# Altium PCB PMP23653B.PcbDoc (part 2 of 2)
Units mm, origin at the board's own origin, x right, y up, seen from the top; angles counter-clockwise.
Board outline 60 x 20 mm, 4 copper layers (Top Layer, Layer 2, Layer 3, Bottom Layer), stack 1.509 mm thick; 89 components, 44 nets, 290 pads, 82 vias.
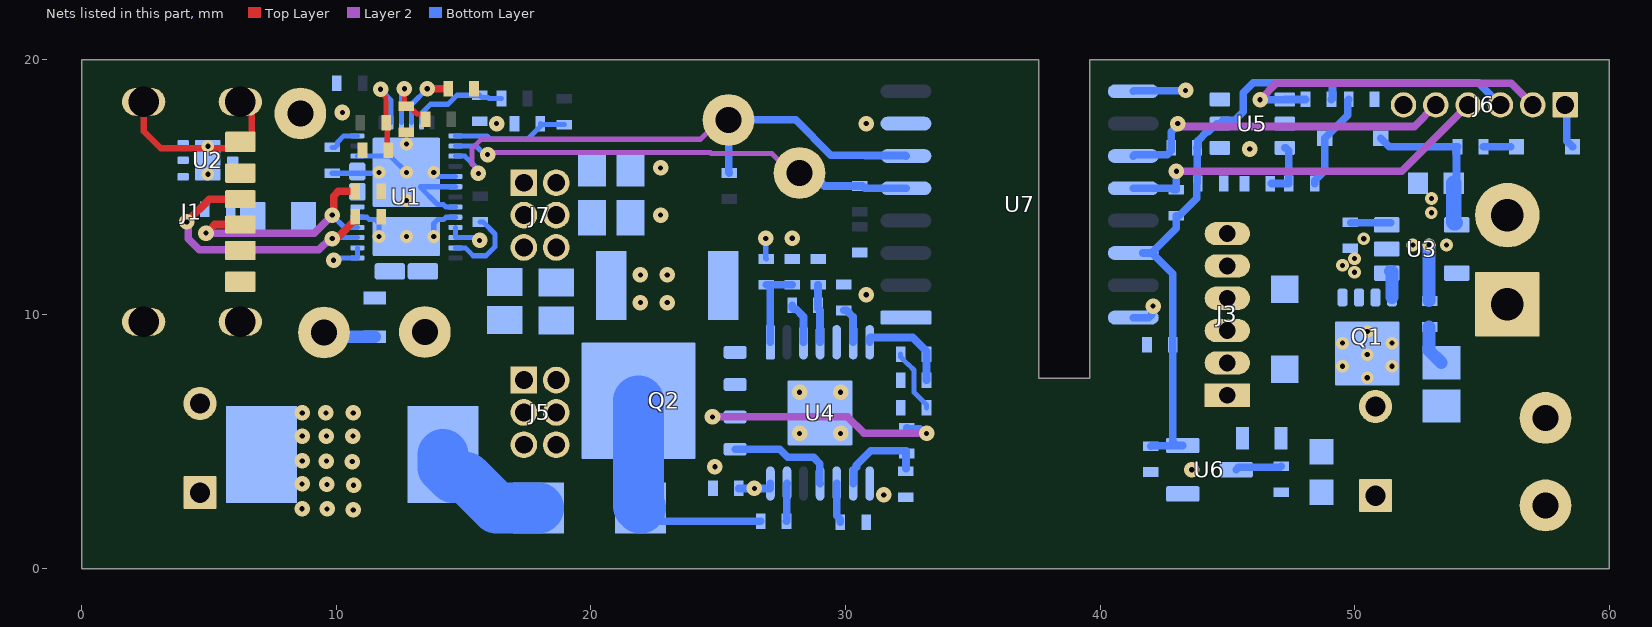
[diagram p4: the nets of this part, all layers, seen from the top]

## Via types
v1: diameter 0.61, hole 0.203, Top Layer to Bottom Layer, tented both sides, 56 vias
v2: diameter 0.5, hole 0.203, Top Layer to Bottom Layer, tented both sides, 9 vias
v3: diameter 0.5, hole 0.2, Top Layer to Bottom Layer, tented both sides, 9 vias
v4: diameter 0.5, hole 0.2, Top Layer to Bottom Layer, 8 vias

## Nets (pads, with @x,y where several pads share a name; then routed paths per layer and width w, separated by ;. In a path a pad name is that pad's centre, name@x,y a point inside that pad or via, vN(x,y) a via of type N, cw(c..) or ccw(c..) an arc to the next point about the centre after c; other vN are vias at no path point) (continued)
3V3S: C21.2 C27.2 C28.2 J6.3 R12.2 R13.2 R26.2 U5.5 U6.2 U7.14 | length 29.4
  Bottom Layer w0.3: U7.14@41.671,12.415 U7.14@42.036,12.415 ; C28.2@42,4.823 42.013,4.836 43.236,4.836 U6.2@43.249,4.85 43.008,4.85 42.858,5 C27.2@42.858,8.8 42.858,11.593 U7.14@42.036,12.415 ; R26.2@49.089,18.445 49.13,18.486 49.13,18.995 49.235,19.1 ; J6.3@55.73,18.23 54.86,19.1 49.235,19.1 ; U7.14@42.036,12.415 43,13.379 R12.2@43,13.877 43.114,13.877 43.801,14.564 43.801,15.136 43.825,15.159 43.825,16.528 R13.2@43.808,16.545 43.849,16.586 43.849,16.828 44.19,17.17 44.256,17.17 44.581,17.495 U5.5@44.706,17.495 44.831,17.62 45.29,17.62 45.63,17.959 45.63,18.706 46.023,19.1 49.235,19.1
ADCIN1: R1.2 R5.2 U1.2 | length 4
  Top Layer w0.2: v1(11.735,18.848) 11.735,18.737 11.953,18.52 R1.2@11.953,17.536 11.997,17.493 11.997,16.496 R5.2@12.04,16.452
  Bottom Layer w0.2: v1(11.735,18.848) 11.735,18.822 12.15,18.408 U1.2@12.15,17.541
ADCIN2: R2.1 R6.1 U1.3 | length 3.1
  Top Layer w0.2: v1(12.673,18.862) 12.673,18.251 R6.1@12.75,18.174 12.864,18.174 13.168,17.871 13.406,17.871 13.497,17.78 R2.1@13.497,17.666
  Bottom Layer w0.2: U1.3@12.55,17.541 12.55,18.628 12.673,18.751 v1(12.673,18.862)
ADCIN3: R3.1 R7.1 U1.5 | length 3.8
  Bottom Layer w0.2: U1.5@13.35,17.541 13.35,17.911 13.696,18.257 14.383,18.257 14.735,18.609 R7.1@15.627,18.609 15.718,18.518 15.96,18.518 15.997,18.482 R3.1@16.487,18.482
ADCIN4: R4.1 R8.1 U1.7 | length 4.7
  Bottom Layer w0.2: U1.7@14.675,17.016 15.919,17.016 16.045,16.89 17.521,16.89 18.011,17.381 R8.1@18.011,17.495 18.05,17.456 R4.1@18.96,17.456
CC1: C5.2 J1.A5 U1.28 | length 11.5
  Top Layer w0.3: v1(4.117,13.632) 5.015,14.53 J1.A5@6.226,14.53 ; v1(9.836,12.979) 9.896,13.038 10.063,13.038 10.742,13.717 C5.2@10.742,13.831
  Layer 2 w0.3: v1(4.117,13.632) 4.177,13.573 4.177,12.968 4.606,12.539 9.312,12.539 9.753,12.979 v1(9.836,12.979)
  Bottom Layer w0.2: v1(9.836,12.979) 9.873,13.016 U1.28@10.825,13.016
CC2: C4.2 J1.B5 U1.29 | length 9.6
  Top Layer w0.3: v1(4.877,13.194) 5.213,13.53 J1.B5@6.226,13.53 ; v1(9.836,13.9) 9.896,13.959 9.896,14.647 10.08,14.831 C4.2@10.742,14.831
  Layer 2 w0.3: v1(4.877,13.194) 9.125,13.194 9.831,13.9 v1(9.836,13.9)
  Bottom Layer w0.2: v1(9.836,13.9) 10.32,13.416 U1.29@10.825,13.416
GND: C1.1 C2.2 C3.2 C4.1 C5.1 C6.1 C7.1 C10.1 C11.2 C12.2 C13.2 C14.2 C19.1 C20.1 C22.1 C23.2 C24.2 C25.1 C30.1 J1.1 J1.2 J1.3 J1.4 J1.A12 J1.B12 R5.1 R6.2 R7.2 R8.2 R23.1 R24.2 R25.2 TP3.1 U1.11 U1.12 U1.14 U1.16 U1.17 U1.26 U1.27 U1.31 U1.34 U1.35 U1.36 U1.39 U2.1 U2.2 U2.3 U2.7@4.95,16.055 U4.5 U4.8 U4.15 U7.1 U7.7 | length 20.4
  Top Layer w0.254: J1.3@2.426,18.35 2.426,17.196 3.096,16.526 6.226,16.526 J1.B12@6.226,16.78 6.277,16.831 6.345,16.763 6.379,16.763 6.67,17.053 6.67,17.959 6.279,18.35 J1.1@6.226,18.35
  Bottom Layer w0.2: C1.1@9.836,15.547 11.641,15.547 v3(11.675,15.581) ; v1(9.89,12.129) 10.001,12.129 10.088,12.216 U1.26@10.825,12.216 U1.27@10.825,12.616 ; U1.36@10.825,16.216 12.115,16.216 v3(12.75,15.581) ; U1.39@13.298,14.999 13.975,14.321 14.2,14.321 14.305,14.216 U1.14@14.675,14.216 ; U1.39@13.315,15.016 U1.12@14.675,15.016 ; U1.39@13.825,15.566 13.975,15.416 U1.11@14.675,15.416 ; U1.16@14.675,13.416 U1.17@14.675,13.016 15.41,13.016 15.516,12.91 v1(15.627,12.91)
  Bottom Layer w0.5: TP3.1@9.516,9.289 9.68,9.125 11.496,9.125 C2.2@11.5,9.121
  other v1: 31.5,2.912 24.87,4.013 28.195,5.323 29.805,5.323 28.195,6.942 29.805,6.942 21.942,10.467 23,10.467 30.813,10.772 21.942,11.553 23,11.553 27.906,12.989 22.736,13.9 22.736,15.756 16.295,17.495 30.813,17.495 10.235,17.932
  other v3: 12.75,14.471 13.825,15.581 12.75,16.691
  other v4: 4.95,15.505 4.95,16.605
NetC1_2: C1.2 U1.38 | length 1.2
  Bottom Layer w0.2: C1.2@9.836,16.563 9.951,16.563 10.041,16.654 10.041,16.768 10.29,17.016 U1.38@10.825,17.016
NetC2_1: C2.1 L1.2 U1.23 U1.24 U1.25 U1.32 U1.33
NetC3_1: C3.1 J1.A9 J1.B9 L1.1 TP1.1 U2.4 U2.5 U2.6
NetC7_2: C7.2 U1.4 | length 2.4
  Top Layer w0.3: v1(13.569,18.862) C7.2@14.392,18.862
  Bottom Layer w0.2: U1.4@12.95,17.541 12.95,18.242 v1(13.569,18.862)
NetC9_1: C9.1 U3.3 | length 1.6
  Bottom Layer w0.3: C9.1@49.853,13.596 U3.3@51.411,13.596
NetC18_1: C18.1 R17.1 | length 1.6
  Bottom Layer w0.5: C18.1@52.92,9.508 52.92,8.588 R17.1@53.408,8.1
NetC20_2: C20.2 U4.10 | length 1.6
  Bottom Layer w0.3: U4.10@29.65,3.357 29.65,2.095 29.797,1.948 C20.2@29.797,1.834
NetC22_2: C22.2 R20.1 U4.9 | length 3.7
  Bottom Layer w0.3: U4.9@30.3,3.357 30.3,3.875 30.43,4.005 30.43,4.08 30.999,4.649 32.374,4.649 C22.2@32.374,3.948
NetC23_1: C23.1 R21.1 U4.7 | length 3.8
  Bottom Layer w0.3: U4.7@30.95,8.908 30.95,9.074 30.969,9.092 32.642,9.092 33.182,8.552 R21.1@33.182,8.438 C23.1@33.182,7.42
NetC24_1: C24.1 R21.2 | length 2.5
  Bottom Layer w0.2: R21.2@32.166,8.438 32.166,8.323 32.465,8.025 32.481,8.025 32.692,7.814 32.692,6.939 33.182,6.449 C24.1@33.182,6.334
NetC25_2: C25.2 U4.6 | length 1.5
  Bottom Layer w0.3: C25.2@29.924,10.156 30.039,10.156 30.292,9.903 30.292,8.916 U4.6@30.3,8.908
NetC26_1: C26.1 D3.1 R27.2 | length 3.9
  Bottom Layer w0.3: R27.2@48.431,15.143 48.431,15.257 48.823,15.649 D3.1@48.823,16.925 49.727,17.828 49.727,18.405 C26.1@49.767,18.445
NetD1_1: D1.1 R15.2 | length 1.1
  Bottom Layer w0.3: R15.2@55.06,16.586 D1.1@56.135,16.586
NetD2_1: D2.1 D4.1 | length 4.9
  Bottom Layer w2: D2.1@14.194,4.5 14.194,3.992 14.591,3.595 15.099,3.595 16.297,2.397 D4.1@17.942,2.397
NetD4_2: D4.2 J5.1 J5.2 J5.3 J5.4 J5.5 J5.6 Q2.5 Q2.6 Q2.7 Q2.8 Q2.9@21.865,6.607 R19.2 | length 9.2
  Bottom Layer w0.3: D4.2@21.942,2.397 22.459,1.88 R19.2@26.667,1.88
  Bottom Layer w2: Q2.9@21.865,6.607 21.865,2.474 D4.2@21.942,2.397
NetQ1_4: Q1.4 U3.1 | length 1.1
  Bottom Layer w0.5: U3.1@51.411,11.696 51.446,11.696 51.471,11.671 Q1.4@51.471,10.665
NetQ2_1: Q2.1 Q2.2 Q2.3 R20.2 R23.2 | length 9.5
  Layer 2 w0.3: v1(24.775,5.972) 24.78,5.977 30.076,5.977 30.728,5.325 v1(33.182,5.325)
  Bottom Layer w0.3: R20.2@32.415,5.548 32.455,5.507 32.916,5.507 33.099,5.325 v1(33.182,5.325)
NetQ2_4: Q2.4 U4.11 | length 4.3
  Bottom Layer w0.3: Q2.4@25.665,4.702 27.412,4.702 27.73,4.385 28.743,4.385 28.992,4.136 28.992,3.365 U4.11@29,3.357
NetR9_1: R9.1 U1.18 | length 3.1
  Bottom Layer w0.2: U1.18@14.675,12.616 15.065,12.616 15.377,12.305 15.878,12.305 16.232,12.659 16.232,13.162 15.765,13.629 R9.1@15.651,13.629
NetR14_2: R14.2 R27.1 U5.3 | length 2.2
  Bottom Layer w0.3: R14.2@46.735,15.143 R27.1@47.415,15.143 47.415,16.42 47.29,16.545 U5.3@47.256,16.545
NetR18_2: R18.2 R24.1 U4.1 | length 3.4
  Bottom Layer w0.3: U4.1@27.05,8.908 27.05,11.116 27.004,11.162 R18.2@26.89,11.162 R24.1@27.906,11.162
NetR19_1: R19.1 U4.13 | length 1.5
  Bottom Layer w0.3: R19.1@27.683,1.88 27.692,1.889 27.692,3.349 U4.13@27.7,3.357
NetR22_1: R22.1 R25.1 U4.4 | length 2.2
  Bottom Layer w0.3: R22.1@28.922,10.239 29,10.161 U4.4@29,8.908 ; R22.1@28.922,10.354 R25.1@28.922,11.162
NetR22_2: R22.2 U4.3 | length 1.7
  Bottom Layer w0.3: R22.2@27.906,10.354 27.906,10.239 27.946,10.199 28.06,10.199 28.35,9.909 U4.3@28.35,8.908
NetU1_15: U1.15 U1.30 U1.40 | length 2.9
  Bottom Layer w0.2: U1.30@10.825,13.816 11.195,13.816 11.29,13.721 11.525,13.721 11.675,13.571 v3(11.675,13.056) ; v3(13.825,13.056) 13.825,13.571 13.975,13.721 14.21,13.721 14.305,13.816 U1.15@14.675,13.816
  other v3: 12.75,13.056
PPHV: C10.2 C11.1 C12.1 C13.1 C14.1 C19.2 D2.2 J7.1 J7.2 J7.3 J7.4 J7.5 J7.6 R18.1 TP2.1 U1.20 U1.21 U1.22 U4.14 | length 2.2
  Bottom Layer w0.2: v1(26.868,12.985) 26.868,12.2 R18.1@26.89,12.178
  Bottom Layer w0.3: C19.2@25.808,3.163 27.031,3.163 27.05,3.182 U4.14@27.05,3.357
  other v1: 10.665,2.318 8.651,2.367 9.635,2.357 26.42,3.163 10.676,3.29 8.651,3.34 9.626,3.319 10.625,4.216 8.66,4.242 9.604,4.236 8.66,5.222 9.604,5.222 10.651,5.222 8.66,6.132 9.589,6.132 10.665,6.132
SCL1: R11.1 TP5.1 U1.9 U7.6 | length 22.6
  Layer 2 w0.2: v1(15.577,15.538) 15.577,15.649 15.332,15.895 15.332,16.527 15.686,16.881 24.299,16.881 25.059,17.641 TP5.1@25.4,17.641
  Bottom Layer w0.2: U1.9@14.675,16.216 15.045,16.216 15.499,15.762 15.499,15.617 v1(15.577,15.538)
  Bottom Layer w0.3: R11.1@25.433,15.553 25.416,15.569 25.416,17.625 TP5.1@25.4,17.641 28.041,17.641 29.427,16.255 30.769,16.255 30.784,16.24 32.359,16.24 U7.6@32.374,16.225
SCL2: J6.5 R13.1 U7.11 | length 13.3
  Layer 2 w0.3: v1(43.054,17.495) 43.138,17.495 43.253,17.38 52.34,17.38 J6.5@53.19,18.23
  Bottom Layer w0.3: U7.11@41.305,16.225 41.352,16.271 42.633,16.271 42.792,16.431 R13.1@42.792,16.545 42.792,17.176 43.054,17.438 v1(43.054,17.495)
SDA1: R10.1 TP4.1 U1.8 U7.5 | length 18.3
  Layer 2 w0.2: v1(15.937,16.276) 16.047,16.276 16.132,16.361 24.689,16.361 24.725,16.325 27.104,16.325 27.874,15.555 TP4.1@28.195,15.555
  Bottom Layer w0.2: U1.8@14.675,16.616 15.486,16.616 15.826,16.276 v1(15.937,16.276)
  Bottom Layer w0.3: TP4.1@28.195,15.555 28.664,15.555 29.174,15.045 R10.1@30.553,15.045 ; R10.1@30.668,15.045 30.757,14.955 U7.5@32.374,14.955
SDA2: J6.4 R12.1 U7.12 | length 15
  Layer 2 w0.3: v1(43,15.625) 51.855,15.625 J6.4@54.46,18.23
  Bottom Layer w0.3: U7.12@41.305,14.955 42.824,14.955 42.886,14.893 R12.1@43,14.893 v1(43,15.625)
SGND: C15.1 C16.1 C17.1 C21.1 C26.2 C27.1 C28.1 J2.2 J3.1 J3.2 J3.3 J6.6 R14.1 R16.1 TP7.1 U5.2 U5.4 U5.6 U6.1 U7.9 U7.16 | length 3.2
  Bottom Layer w0.3: U7.16@41.305,9.875 41.915,9.875 42.027,9.987 42.027,10.267 v1(42.086,10.326) ; U7.9@41.305,18.765 41.323,18.783 43.339,18.783 v1(43.357,18.801)
  other v1: 43.599,3.9 45.878,16.498
VIN_MAG: J6.2 R26.1 U5.1 | length 13.1
  Layer 2 w0.3: v1(46.284,18.435) 46.93,19.08 56.15,19.08 J6.2@57,18.23
  Bottom Layer w0.3: v1(46.284,18.435) 46.289,18.44 47.251,18.44 U5.1@47.256,18.445 R26.1@48.073,18.445
VMON: C8.1 D3.2 R15.1 U3.4 | length 6.3
  Bottom Layer w0.3: D3.2@51.023,16.925 51.362,16.586 R15.1@54.044,16.586 54.004,16.545 54.004,15.273 C8.1@53.89,15.159
  Bottom Layer w0.6: C8.1@53.89,15.159 53.89,13.621 53.915,13.596 U3.4@53.961,13.596
VOUT: C15.2 C16.2 C17.2 D1.2 D5.C J2.1 J6.1 Q1.5 Q1.6 Q1.7 Q1.8 Q1.9 R16.2 R17.2 TP6.1 U3.5 U6.3 | length 3.6
  Bottom Layer w0.3: U6.3@45.349,3.9 45.438,3.988 47.076,3.988 C17.2@47.116,4.029 ; J6.1@58.27,18.23 58.335,18.165 58.335,16.812 D1.2@58.561,16.586
  other v3: 50.496,7.512
  other v4: 49.521,7.965 51.471,7.965 50.496,8.417 49.521,8.87 51.471,8.87 50.496,9.322
VSEC: C8.2 C9.2 C18.2 D5.A J3.4 J3.5 J3.6 Q1.1 Q1.2 Q1.3 U3.2 | length 2.2
  Bottom Layer w0.5: C18.2@52.92,10.543 v2(52.92,12.729)
  other v2: 49.999,11.657 49.521,11.927 49.999,12.191 52.288,12.729 53.611,12.729 50.357,12.975 53.016,13.991 53.02,14.556
pads on no net: Q1.9A Q1.9B Q1.9C Q1.9D Q2.9@21.47,5.157 Q2.9@21.47,6.607 Q2.9@21.47,8.057 Q2.9@22.32,6.607 Q2.9@23.25,5.157 Q2.9@23.25,6.607 Q2.9@23.25,8.057 U1.6 U1.10 U1.13 U1.19 U1.37 U2.7@4.95,15.605 U2.7@4.95,16.505 U4.2 U4.12 U7.2 U7.4 U7.8 U7.10 U7.13 U7.15

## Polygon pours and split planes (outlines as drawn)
SGND on Top Layer "TOP_LAYER_SGND_P014" (solid, remove dead copper, pour order 14): 41.581,20.019 41.581,0 60.018,0 60.018,20.019
GND on Top Layer "TOP_LAYER_GND_P008" (solid, remove dead copper, pour order 8): 0,20.019 0,0 32.415,0 32.415,20.019
NetC3_1 on Top Layer "TOP_LAYER_NETC3_1_P000" (solid, remove dead copper, pour order 0): 5.5,18.949 5.5,12.129 9.686,12.129 9.686,18.949
SGND on Bottom Layer "BOTTOM_LAYER_SGND_P011" (solid, remove dead copper, pour order 11): 41.581,20 41.581,0 60,0 60,20
VOUT on Bottom Layer "BOTTOM_LAYER_VOUT_P010" (solid, remove dead copper, pour order 10): 46.362,11.935 46.362,3.78 60,3.78 60,11.935
VSEC on Bottom Layer "BOTTOM_LAYER_VSEC_P001" (solid, remove dead copper, pour order 1): 52.016,13.776 52.012,13.781 52.012,15.715 53.263,15.715 53.357,15.622 53.357,13.98 54.326,13.98 54.53,13.776 54.53,11.966 53.535,11.966 51.725,10.156 44.048,10.156 44.048,13.776
GND on Bottom Layer "BOTTOM_LAYER_GND_P009" (solid, remove dead copper, pour order 9): 0,20.008 0,0 32.415,0 32.415,20.008
PPHV on Bottom Layer "BOTTOM_LAYER_PPHV_P004" (solid, remove dead copper, pour order 4): 3.75,16.605 3.75,10.505 20.62,10.505 20.62,16.605
NetQ2_1 on Bottom Layer "BOTTOM_LAYER_NETQ2_1_P007" (solid, remove dead copper, pour order 7): 24.365,12.598 24.365,5.547 26.5,5.547 26.5,12.598
NetD4_2 on Bottom Layer "BOTTOM_LAYER_NETD4_2_P006" (solid, remove dead copper, pour order 6): 15.959,8.908 15.959,3.883 24.2,3.883 24.2,8.908
PPHV on Bottom Layer "BOTTOM_LAYER_PPHV_P005" (solid, remove dead copper, pour order 5): 0,12.008 0,0 15.627,0 15.627,12.008
NetC2_1 on Bottom Layer "BOTTOM_LAYER_NETC2_1_P002" (solid, remove dead copper, pour order 2): 7.5,15.188 7.5,10.367 12.595,10.367 12.595,15.188
NetC3_1 on Bottom Layer "BOTTOM_LAYER_NETC3_1_P003" (solid, remove dead copper, pour order 3): 5.385,18.955 5.385,12.764 9.766,12.764 9.766,18.955
SGND on Layer 2 "LAYER_2_SGND_P013" (solid, remove dead copper, pour order 13): 41.581,20 41.581,0 60,0 60,20
GND on Layer 2 "LAYER_2_GND_P016" (solid, remove dead copper, pour order 16): 0.667,20 0.667,0 32.374,0 32.374,20
VSEC on Layer 3 "LAYER_3_VSEC_P012" (solid, remove dead copper, pour order 12): 51.212,13.776 52.012,14.576 52.012,15.715 54.514,15.715 54.525,15.726 54.53,15.721 54.53,11.276 53.722,11.276 52.279,9.834 49.289,9.834 49.289,13.776
VOUT on Layer 3 "LAYER_3_VOUT_P015" (solid, remove dead copper, pour order 15): 41.581,20.019 41.581,0 60,0 60,20.019
PPHV on Layer 3 "LAYER_3_PPHV_P017" (solid, remove dead copper, pour order 17): 0,20 0,0 32.417,0 32.417,20

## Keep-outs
Keep-Out Layer:
  text ".Layer_Name" at 14.656,-21.806 h1.52

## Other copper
Top Layer:
  text ".Layer_Name" at 14.656,-21.806 h1.52
Bottom Layer:
  text ".Layer_Name" at 14.656,-21.806 h1.52

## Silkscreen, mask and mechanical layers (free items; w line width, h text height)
Top Overlay:
  text "'.PRJ_Number'.PCB_Rev" at 26.021,4.242 h2
  text "For Demo Purposes Only." at 17.073,2.356 h2
  text "Not for Diagnostic or Therapeutic Use." at 17.083,0.692 h2
  text ".Layer_Name" at 14.656,-21.806 h1.52
Bottom Overlay:
  text ".Layer_Name" at 14.656,-21.806 h1.52
Top Paste:
  text ".Layer_Name" at 14.656,-21.806 h1.52
Bottom Paste:
  text ".Layer_Name" at 14.656,-21.806 h1.52
Top Solder:
  text ".Layer_Name" at 14.656,-21.806 h1.52
  text ".Layer_Name" at 14.656,-21.806 h1.52
Bottom Solder:
  text ".Layer_Name" at 14.656,-21.806 h1.52
Drill Guide:
  text ".Layer_Name" at 14.656,-21.806 h1.52
M1 Board Outline:
  lines w0.1: -0.05,0 ccw(c0,0) 0,-0.05 ; -0.05,0 ccw(c0,0) 0,-0.05 ; -0.05,0 -0.05,20 ; -0.05,20 cw(c0,20) 0,20.05 ; -0.05,20 cw(c0,20) 0,20.05 ; 0,-0.05 60,-0.05 ; 0,20.05 37.6,20.05 ; 37.55,7.5 ccw(c37.6,7.5) 37.6,7.45 ; 37.55,7.5 ccw(c37.6,7.5) 37.6,7.45 ; 37.55,7.5 37.55,19.95 0.05,19.95 0.05,0.05 59.95,0.05 59.95,19.95 39.65,19.95 39.65,7.5 ; 37.6,7.45 39.6,7.45 ; 37.6,20.05 cw(c37.6,20) 37.65,20 ; 37.6,20.05 cw(c37.6,20) 37.65,20 ; 37.65,20 37.65,7.55 39.55,7.55 39.55,20 ; 39.55,20 cw(c39.6,20) 39.6,20.05 ; 39.55,20 cw(c39.6,20) 39.6,20.05 ; 39.6,7.45 ccw(c39.6,7.5) 39.65,7.5 ; 39.6,7.45 ccw(c39.6,7.5) 39.65,7.5 ; 39.6,20.05 60,20.05 ; 60,-0.05 ccw(c60,0) 60.05,0 ; 60,-0.05 ccw(c60,0) 60.05,0 ; 60,20.05 cw(c60,20) 60.05,20 ; 60,20.05 cw(c60,20) 60.05,20 ; 60.05,0 60.05,20 ; 0,0 60,0 60,20 39.6,20 39.6,7.5 37.6,7.5 37.6,20 0,20 0,0
  text ".Layer_Name" at 14.656,-21.806 h1.52
M2 Board Dimensions:
  rectangle: 0,-6.985 3.175,-3.81
  rectangle: 3.175,-10.16 12.7,-6.985
  lines w0.178: 0,-6.985 25.4,-6.985 ; 3.175,-10.16 3.175,-3.81 ; 6.35,-10.16 6.35,-3.81 ; 12.7,-10.16 12.7,-3.81 ; 19.05,-10.16 19.05,-3.81 ; 0,-10.16 25.4,-10.16 25.4,-3.81 0,-3.81 0,-10.16
  text ".Layer_Name" at 14.656,-21.806 h1.52
M3 3D STEP Top:
  text ".Layer_Name" at 14.656,-21.806 h1.52
M4 3D STEP Bottom:
  text ".Layer_Name" at 14.656,-21.806 h1.52
Top Assembly:
  lines w0.254: -7.417,-23.626 160.223,-23.626 ; -7.417,-18.462 160.274,-18.462 ; -7.417,-13.297 -7.417,-28.791 94.31,-28.791 160.274,-28.791 160.274,-13.297 -7.404,-13.297 -7.404,-28.791 32.614,-28.791 ; 55.194,-28.791 55.194,-13.297 ; 87.376,-18.462 87.376,-13.297 ; 108.712,-18.462 108.712,-13.297 ; 124.511,-28.956 124.511,-23.804
  text "COMPONENTS MARKED 'DNP' SHOULD NOT BE POPULATED." at 29.299,-8.09 h1.52
  text "ASSEMBLY VARIANT:" at 29.286,-11.024 h1.52
  text ".VariantName" at 55.601,-11.024 h1.52
  text "PCB VIEWED FROM TOP SIDE" at -5.804,-16.654 h1.52
  text "BOARD #:" at 57.099,-16.654 h1.52
  text ".PRJ_Number" at 70.955,-16.654 h1.52
  text "REV:" at 92.405,-16.654 h1.52
  text ".PCB_Rev" at 99.809,-16.654 h1.52
  text "SVN REV:" at 113.69,-16.654 h1.52
  text ".VersionControl_RevNumber" at 126.543,-16.654 h1.52
  text "TID #:" at 57.099,-21.819 h1.52
  text ".TID" at 70.955,-21.819 h1.52
  text "PLOT NAME =" at -5.804,-27.034 h1.52
  text ".plot_File_Name" at 14.656,-27.034 h1.52
  text "GENERATED    :" at 57.15,-27.034 h1.52
  text ".Print_Date" at 79.235,-27.034 h1.52
  text ".Print_Time" at 97.752,-27.034 h1.52
  text "TEXAS INSTRUMENTS" at 129.87,-27.034 h1.52
Bottom Assembly:
  lines w0.254: -7.429,-18.474 160.261,-18.474 ; -7.379,-23.639 160.261,-23.639 ; 28.334,-28.969 28.334,-23.817 ; 44.133,-18.474 44.133,-13.31 ; 65.468,-18.474 65.468,-13.31 ; 97.65,-28.804 97.65,-13.31 ; 120.231,-28.804 160.249,-28.804 160.249,-13.31 -7.429,-13.31 -7.429,-28.804 58.534,-28.804 160.261,-28.804 160.261,-13.31
  text "COMPONENTS MARKED 'DNP' SHOULD NOT BE POPULATED." at 154.991,-8.077 h1.52
  text ".VariantName" at 128.473,-11.024 h1.52
  text "ASSEMBLY VARIANT:" at 154.864,-11.024 h1.52
  text ".VersionControl_RevNumber" at 26.302,-16.667 h1.52
  text "SVN REV:" at 39.154,-16.667 h1.52
  text ".PCB_Rev" at 53.035,-16.667 h1.52
  text "REV:" at 60.439,-16.667 h1.52
  text ".PRJ_Number" at 81.89,-16.667 h1.52
  text "BOARD #:" at 95.745,-16.667 h1.52
  text "PCB VIEWED FROM BOTTOM SIDE" at 158.648,-16.667 h1.52
  text ".TID" at 81.89,-21.831 h1.52
  text "TID #:" at 95.745,-21.831 h1.52
  text "TEXAS INSTRUMENTS" at 22.974,-27.047 h1.52
  text ".Print_Time" at 55.093,-27.047 h1.52
  text ".Print_Date" at 73.609,-27.047 h1.52
  text "GENERATED    :" at 95.694,-27.047 h1.52
  text ".plot_File_Name" at 138.189,-27.047 h1.52
  text "PLOT NAME =" at 158.648,-27.047 h1.52
M9 Title Sheet:
  drawing of 57 lines, arcs and shapes, not listed
  text "1" at 18.792,204.127 h1.78
  text "2" at 82.182,204.127 h1.78
  text "3" at 145.411,204.127 h1.78
  text "4" at 209.08,204.127 h1.78
  text "5" at 272.555,204.127 h1.78
  text "6" at 336.182,204.127 h1.78
  text "A" at -10.579,175.095 h1.78
  text "A" at 365.341,175.095 h1.78
  text "B" at -10.579,114.643 h1.78
  text "B" at 365.341,114.643 h1.78
  text "C" at -10.579,54.318 h1.78
  text "C" at 365.341,54.318 h1.78
  text "PROJECT TITLE:" at 288.125,7.048 h1.14
  text ".PRJ_Title" at 289.395,3.662 h1.78
  text "DESIGNED FOR:" at 288.125,-0.597 h1.14
  text ".PRJ_Customer" at 289.395,-4.153 h1.78
  text "D" at -10.579,-5.88 h1.78
  text "D" at 365.341,-5.88 h1.78
  text "FILE NAME:" at 288.125,-8.217 h1.14
  text ".PCB_File_Name_No_Path" at 289.395,-11.265 h1.78
  text "Texas Instruments (TI) and/or its licensors do not warrant the accuracy or completeness of this specification" at 161.9,-15.376 h1.14
  text "ENGINEER:" at 288.125,-15.583 h1.14
  text "LAYOUT BY:" at 326.352,-15.583 h1.14
  text "or any information contained therein. TI and/or its licensors do not warrant that this design will meet" at 160.757,-18.237 h1.14
  text ".PRJ_Engineer" at 289.395,-19.52 h1.78
  text ".PCB_Layout" at 327.635,-19.52 h1.78
  text "the specifications, will be suitable for your application or fit for any particular purpose, or will operate in" at 160.757,-21.099 h1.14
  text ".Layer_Name" at 14.656,-21.806 h1.52
  text "ALTIUM DESIGNER VERSION:" at 326.352,-23.457 h1.14
  text "an implementation. TI and/or its licensors do not warrant that the design is production worthy. You should" at 160.757,-23.961 h1.14
  text "completely validate and test your design implementation to confirm the system functionality for your application." at 161.9,-26.822 h1.14
  text ".print_Scale" at 289.395,-26.843 h1.78
  text ".Application_BuildNumber" at 327.635,-26.843 h1.78
  text "1" at 18.792,-32.093 h1.78
  text "2" at 82.182,-32.093 h1.78
  text "3" at 145.411,-32.093 h1.78
  text "4" at 209.08,-32.093 h1.78
  text "5" at 272.555,-32.093 h1.78
  text "6" at 336.182,-32.093 h1.78
M10 Fab Notes:
  drawing of 189 lines, arcs and shapes, not listed
  text "DESIGN INFORMATION" at 314.503,161.447 h1.52
  text "MIN. TRACK WIDTH:" at 298.131,158.091 h1.52
  text "8" at 325.976,158.091 h1.52
  text "MIL" at 329.907,158.091 h1.52
  text "7.874" at 321.75,155 h1.52
  text "MIN. CLEARANCE:" at 298.131,154.938 h1.52
  text "MIL" at 329.907,154.938 h1.52
  text "MIN. VIA PAD SIZE:" at 298.131,151.785 h1.52
  text "24" at 325.214,151.785 h1.52
  text "MIL" at 329.907,151.785 h1.52
  text "0.05mm (2MIL)" at 315.784,148.486 h1.52
  text "MINIMUM ANNULAR RING" at 289.769,148.277 h1.52
  text "EXTERNAL" at 333.768,148.277 h1.52
  text "PER" at 294.849,145.48 h1.52
  text "IPC-D-275 CLASS 2 LEVEL C" at 300.437,145.48 h1.52
  text "MIL, HOLES" at 338.238,142.928 h1.52
  text "+/-" at 328.27,142.709 h1.52
  text "+/-" at 349.961,142.709 h1.52
  text "REGISTRATION TOLERANCES:" at 289.769,142.682 h1.52
  text "METAL" at 320.243,142.682 h1.52
  text "5" at 334.879,142.683 h1.52
  text "3" at 356.037,142.683 h1.52
  text "MIL" at 358.99,142.682 h1.52
  text "HOLE SIZE TOLERANCE (UNLESS OTHERWISE SPECIFIED):" at 289.769,140.185 h1.52
  text "+/-" at 349.961,140.112 h1.52
  text "3" at 356.037,140.085 h1.52
  text "MIL" at 358.99,140.085 h1.52
  text "MATERIAL:" at 287.87,136.589 h1.52
  text "FR-4 High Tg" at 312.926,133.324 h1.52
  text "FR-4" at 298.563,133.007 h1.52
  text "X" at 331.75,133.007 h1.52
  text "OTHER" at 336.358,133.007 h1.52
  text "KB-6165 TG155" at 344.359,133.007 h1.52
  text "62 MIL (1.6mm) +/-10%" at 306.694,129.374 h1.52
  text "X" at 303.643,129.312 h1.52
  text "THICKNESS:" at 289.769,129.165 h1.52
  text "OTHER" at 339.33,129.165 h1.52
  text "TOLERANCE:" at 289.769,125.652 h1.52
  text "X" at 311.314,125.652 h1.52
  text "ANSI IPC-6012 TYPE 3 CLASS 2" at 315.836,125.652 h1.52
  text "OTHER +/-" at 315.835,121.989 h1.52
  text "BOW & TWIST:" at 289.769,118.302 h1.52
  text "X" at 311.314,118.302 h1.52
  text "ANSI IPC-6012 TYPE 3 CLASS 2" at 315.836,118.302 h1.52
  text "OTHER +/-" at 315.835,114.576 h1.52
  text "DRILLING:" at 287.87,111.258 h1.52
  text "NC_DRILL FILES" at 332.599,108.586 h1.52
  text "REFERENCE:" at 289.769,108.486 h1.52
  text "X" at 306.463,108.484 h1.52
  text "AS SHOWN" at 310.984,108.486 h1.52
  text "X" at 329.348,108.486 h1.52
  text "OTHER" at 340.168,104.873 h1.52
  text "PTH COPPER THICKNESS:" at 289.761,104.783 h1.52
  text "X" at 318.697,104.783 h1.52
  text "20-30 um" at 321.948,104.783 h1.52
  text "BOARD FINISH:" at 287.87,101.034 h1.52
  text "SILKSCREEN:" at 291.812,98.237 h1.52
  text "X" at 316.14,98.237 h1.52
  text "TOP" at 319.112,98.237 h1.52
  text "X" at 329.094,98.237 h1.52
  text "BOTTOM" at 332.091,98.237 h1.52
  text "SILKSCREEN COLOR:" at 291.812,94.295 h1.52
  text "X" at 316.115,94.295 h1.52
  text "WHITE" at 319.112,94.295 h1.52
  text "OTHER" at 332.091,94.295 h1.52
  text "X" at 319.442,90.652 h1.52
  text "GREEN" at 322.439,90.652 h1.52
  text "OTHER" at 338.136,90.652 h1.52
  text "SOLDER RESIST COLOR:" at 291.812,90.477 h1.52
  text "X" at 319.442,86.734 h1.52
  text "MATTE" at 322.439,86.734 h1.52
  text "SEMI-GLOSS" at 338.125,86.717 h1.52
  text "IMMERSION GOLD (ENIG)" at 314.819,82.345 h1.52
  text "ENEPIG" at 348.793,82.162 h1.52
  text "SURFACE FINISH:" at 287.87,82.136 h1.52
  text "X" at 310.298,82.136 h1.52
  text "IMM. TIN/SILVER OR EQUIV" at 296.24,78.649 h1.52
  text "OTHER" at 332.599,78.549 h1.52
  text "ARRAY/PANEL:" at 287.87,74.602 h1.52
  text "CUT AND TRIM PER M1 BOARD OUTLINE" at 314.819,74.393 h1.52
  text "N.C. ROUTE" at 314.819,70.94 h1.52
  text "X" at 332.295,70.94 h1.52
  text "V. SCORE" at 336.816,70.94 h1.52
  text "CERTIFICATION:" at 287.87,67.66 h1.52
  text "MATERIALS AND WORKMANSHIP FOR ALL PCBS" at 306.285,67.66 h1.52
  text "TO MEET OR EXCEED THE REQUIREMENTS OF:" at 306.285,65.271 h1.52
  text "X" at 297.078,62.003 h1.52
  text "ANSI IPC-A-600F CLASS ->" at 300.329,62.003 h1.52
  text "X" at 342.188,62.003 h1.52
  text "2" at 344.982,62.003 h1.52
  text "1" at 336.981,61.965 h1.52
  text "3" at 353.973,61.965 h1.52
  text "X" at 317.702,58.252 h1.52
  text "RoHS" at 320.953,58.252 h1.52
  text "OTHER" at 337.321,58.252 h1.52
  text "PER ORDER" at 347.407,58.252 h1.52
  text "ALL BOARDS MUST MEET OR EXCEED UL94-V0 REQUIREMENTS." at 288.569,54.345 h1.52
  text "PCB MUST BEAR THE UL94V-0 UL REGISTERED MATERIAL ID NUMBER" at 288.569,51.397 h1.52
  text "ADDITIONAL REQUIREMENTS:" at 287.87,47.094 h1.52
  text "MICROSECTION:" at 289.769,44.373 h1.52
  text "YES" at 312.775,44.373 h1.52
  text "REQUIRED" at 334.657,40.707 h1.52
  text "BARE BOARD ELEC. TEST:" at 289.769,40.634 h1.52
  text "NONE" at 322.935,40.634 h1.52
  text "X" at 331.66,40.634 h1.52
  text "PER ORDER" at 349.693,40.634 h1.52
  text "XX MIL VIAS REQUIRE NON-CONDUCTIVE FILL AND PLANARIZE" at 294.04,35.428 h1.5
  text "XX MIL VIAS REQUIRE CONDUCTIVE FILL AND PLANARIZE" at 294.243,32.787 h1.52
  text "OUTER XX MIL TRACES REQUIRE 50 OHM SINGLE-ENDED IMPEDANCE" at 294.218,28.637 h1.47
  text "LAYER 2 & 3 (INNER LAYERS) XX MIL WIDE, XX MIL SPACE / TRACES REQUIRE 100 OHM DIFFERENTIAL IMPEDANCE" at 294.015,22.65 h1.52
  text ".Layer_Name" at 14.656,-21.806 h1.52
M11 Gerber Information:
  lines w0.254: -7.417,-23.626 160.223,-23.626 ; -7.417,-18.462 160.274,-18.462 ; -7.417,-13.297 -7.417,-28.791 94.31,-28.791 160.274,-28.791 160.274,-13.297 -7.404,-13.297 -7.404,-28.791 32.614,-28.791 ; 55.194,-28.791 55.194,-13.297 ; 87.376,-18.462 87.376,-13.297 ; 108.712,-18.462 108.712,-13.297 ; 124.511,-28.956 124.511,-23.804
  text "ALL ARTWORK VIEWED FROM TOP SIDE" at -5.804,-16.654 h1.52
  text "BOARD #:" at 57.099,-16.654 h1.52
  text ".PRJ_Number" at 70.955,-16.654 h1.52
  text "REV:" at 92.405,-16.654 h1.52
  text ".PCB_Rev" at 99.809,-16.654 h1.52
  text "SVN REV:" at 113.69,-16.654 h1.52
  text ".VersionControl_RevNumber" at 126.543,-16.654 h1.52
  text "LAYER NAME =" at -5.804,-21.806 h1.52
  text "TID #:" at 57.099,-21.819 h1.52
  text ".TID" at 70.955,-21.819 h1.52
  text "PLOT NAME =" at -5.804,-27.034 h1.52
  text ".plot_File_Name" at 14.656,-27.034 h1.52
  text "GENERATED    :" at 57.15,-27.034 h1.52
  text ".Print_Date" at 79.235,-27.034 h1.52
  text ".Print_Time" at 97.752,-27.034 h1.52
  text "TEXAS INSTRUMENTS" at 129.87,-27.034 h1.52
M12 Stackup:
  drawing of 399 lines, arcs and shapes, not listed
  text "Layer" at 249.469,200.023 h1.52
  text "Name" at 259.88,200.023 h1.52
  text "Material" at 293.653,200.023 h1.52
  text "Thickness" at 308.889,200.023 h1.52
  text "Constant" at 325.395,200.023 h1.52
  text "Board Layer Stack" at 339.869,200.023 h1.52
  text "Top Overlay" at 259.88,196.975 h1.52
  text "Top Solder" at 259.88,193.927 h1.52
  text "SM-001" at 293.653,193.927 h1.52
  text "1.00mil" at 308.889,193.927 h1.52
  text "4" at 325.395,193.927 h1.52
  text "Top Surface Finish" at 259.88,190.879 h1.52
  text "PbSn" at 293.653,190.879 h1.52
  text "0.79mil" at 308.889,190.879 h1.52
  text "1" at 249.469,187.831 h1.52
  text "Top Layer" at 259.88,187.831 h1.52
  text "CF-005" at 293.653,187.831 h1.52
  text "2.76mil" at 308.889,187.831 h1.52
  text "Dielectric 1" at 259.88,184.783 h1.52
  text "PP-017" at 293.653,184.783 h1.52
  text "5.10mil" at 308.889,184.783 h1.52
  text "4.3" at 325.395,184.783 h1.52
  text "Dielectric 2" at 259.88,181.735 h1.52
  text "PP-017" at 293.653,181.735 h1.52
  text "5.10mil" at 308.889,181.735 h1.52
  text "4.3" at 325.395,181.735 h1.52
  text "2" at 249.469,178.687 h1.52
  text "Layer 2" at 259.88,178.687 h1.52
  text "CF-005" at 293.653,178.687 h1.52
  text "2.76mil" at 308.889,178.687 h1.52
  text "Dielectric 3" at 259.88,175.639 h1.52
  text "Core-039" at 293.653,175.639 h1.52
  text "28.00mil" at 308.889,175.639 h1.52
  text "4.8" at 325.395,175.639 h1.52
  text "3" at 249.469,172.591 h1.52
  text "Layer 3" at 259.88,172.591 h1.52
  text "CF-005" at 293.653,172.591 h1.52
  text "2.76mil" at 308.889,172.591 h1.52
  text "Dielectric 4" at 259.88,169.543 h1.52
  text "PP-017" at 293.653,169.543 h1.52
  text "5.10mil" at 308.889,169.543 h1.52
  text "4.3" at 325.395,169.543 h1.52
  text "Dielectric 5" at 259.88,166.495 h1.52
  text "PP-017" at 293.653,166.495 h1.52
  text "5.10mil" at 308.889,166.495 h1.52
  text "4.3" at 325.395,166.495 h1.52
  text "4" at 249.469,163.447 h1.52
  text "Bottom Layer" at 259.88,163.447 h1.52
  text "CF-005" at 293.653,163.447 h1.52
  text "2.76mil" at 308.889,163.447 h1.52
  text "Bottom Surface Finish" at 259.88,160.399 h1.52
  text "PbSn" at 293.653,160.399 h1.52
  text "0.79mil" at 308.889,160.399 h1.52
  text "Bottom Solder" at 259.88,157.351 h1.52
  text "SM-001" at 293.653,157.351 h1.52
  text "1.00mil" at 308.889,157.351 h1.52
  text "4" at 325.395,157.351 h1.52
  text "Bottom Overlay" at 259.88,154.303 h1.52
  text ".Layer_Name" at 14.656,-21.806 h1.52
M13 Component Bodies Top:
  text ".Layer_Name" at 14.656,-21.806 h1.52
M14 Component Bodies Bottom:
  text ".Layer_Name" at 14.656,-21.806 h1.52
M15 Courtyards Top:
  text ".Layer_Name" at 14.656,-21.806 h1.52
M16 Courtyards Bottom:
  text ".Layer_Name" at 14.656,-21.806 h1.52
Drill Drawing:
  circle w0.254: c66.344,20.308 r0.702
  lines w0.254: 65.642,3.817 66.344,4.168 67.046,3.817 66.695,4.519 67.046,5.221 66.344,4.87 65.642,5.221 65.993,4.519 65.642,3.817 ; 65.642,7.326 65.993,7.326 66.344,6.975 66.695,7.326 67.046,7.326 66.695,7.677 67.046,8.028 66.695,8.028 66.344,8.379 65.993,8.028 65.642,8.028 65.993,7.677 65.642,7.326 ; 65.642,10.484 65.993,10.484 65.993,10.133 66.695,10.133 66.695,10.484 67.046,10.484 67.046,11.185 66.695,11.185 66.695,11.536 65.993,11.536 65.993,11.185 65.642,11.185 65.642,10.484 ; 65.642,14.694 67.046,14.694 66.344,13.291 65.642,14.694 ; 65.642,16.448 67.046,16.448 67.046,17.852 65.642,17.852 65.642,16.448 ; 65.642,23.466 66.344,22.764 67.046,23.466 66.344,24.167 65.642,23.466 ; 65.642,25.922 65.642,26.272 65.993,26.623 65.642,26.974 65.642,27.325 65.993,27.325 66.344,26.974 66.695,27.325 67.046,27.325 67.046,26.974 66.695,26.623 67.046,26.272 67.046,25.922 66.695,25.922 66.344,26.272 65.993,25.922 65.642,25.922
  lines w0.305: 64.37,2.87 146.45,2.87 ; 64.37,28.132 146.45,28.132 ; 72.952,-0.288 72.952,31.29 ; 81.384,-0.288 81.384,31.29 ; 97.553,-0.288 97.553,31.29 ; 104.135,-0.288 104.135,31.29 ; 113.664,-0.288 113.664,31.29 ; 132.062,-0.288 132.062,31.29 ; 64.37,-0.288 146.45,-0.288 146.45,31.29 64.37,31.29 64.37,-0.288
  text "Symbol" at 66.265,29.079 h1.83
  text "Quantity" at 73.899,29.079 h1.83
  text "Finished Hole Size" at 82.332,29.079 h1.83
  text "Plated" at 98.501,29.079 h1.83
  text "Hole Type" at 105.083,29.079 h1.83
  text "Drill Layer Pair" at 114.612,29.079 h1.83
  text "Hole Tolerance" at 133.01,29.079 h1.83
  text "17" at 73.899,25.922 h1.52
  text "7.87mil (0.200mm)" at 82.332,25.922 h1.52
  text "PTH" at 98.501,25.922 h1.52
  text "Round" at 105.083,25.922 h1.52
  text "Top Layer - Bottom Layer" at 114.612,25.922 h1.52
  text "65" at 73.899,22.764 h1.52
  text "8.00mil (0.203mm)" at 82.332,22.764 h1.52
  text "PTH" at 98.501,22.764 h1.52
  text "Round" at 105.083,22.764 h1.52
  text "Top Layer - Bottom Layer" at 114.612,22.764 h1.52
  text "6" at 73.899,19.606 h1.52
  text "26.00mil (0.660mm)" at 82.332,19.606 h1.52
  text "PTH" at 98.501,19.606 h1.52
  text "Round" at 105.083,19.606 h1.52
  text "Top Layer - Bottom Layer" at 114.612,19.606 h1.52
  text "18" at 73.899,16.448 h1.52
  text "27.56mil (0.700mm)" at 82.332,16.448 h1.52
  text "PTH" at 98.501,16.448 h1.52
  text "Round" at 105.083,16.448 h1.52
  text "Top Layer - Bottom Layer" at 114.612,16.448 h1.52
  text "4" at 73.899,13.291 h1.52
  text "31.50mil (0.800mm)" at 82.332,13.291 h1.52
  text "PTH" at 98.501,13.291 h1.52
  text "Round" at 105.083,13.291 h1.52
  text "Top Layer - Bottom Layer" at 114.612,13.291 h1.52
  text "7" at 73.899,10.133 h1.52
  text "40.00mil (1.016mm)" at 82.332,10.133 h1.52
  text "PTH" at 98.501,10.133 h1.52
  text "Round" at 105.083,10.133 h1.52
  text "Top Layer - Bottom Layer" at 114.612,10.133 h1.52
  text "2" at 73.899,6.975 h1.52
  text "50.00mil (1.270mm)" at 82.332,6.975 h1.52
  text "PTH" at 98.501,6.975 h1.52
  text "Round" at 105.083,6.975 h1.52
  text "Top Layer - Bottom Layer" at 114.612,6.975 h1.52
  text "4" at 73.899,3.817 h1.52
  text "47.24mil (1.200mm)" at 82.332,3.817 h1.52
  text "PTH" at 98.501,3.817 h1.52
  text "Slot" at 105.083,3.817 h1.52
  text "Top Layer - Bottom Layer" at 114.612,3.817 h1.52
  text "123 Total" at 73.899,0.66 h1.52
  text "Slot definitions :" at 66.265,-1.551 h1.52
  text "Routed Path Length" at 77.713,-1.551 h1.52
  text "= Calculated from tool start centre position to tool end centre position." at 91.422,-1.551 h1.52
  text "Hole Length" at 77.713,-2.814 h1.52
  text "= Routed Path Length + Tool Size = Slot length as defined in the PCB layout" at 86.347,-2.814 h1.52
  text ".Layer_Name" at 14.656,-21.806 h1.52
M17 Embedded Cavity:
  text ".Layer_Name" at 14.656,-21.806 h1.52
M18 Embedded Assembly:
  text ".Layer_Name" at 14.656,-21.806 h1.52
M19 Embedded Keepout:
  text ".Layer_Name" at 14.656,-21.806 h1.52

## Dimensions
0,-10.16 to 25.4,-10.16 on M2 Board Dimensions
-1,20 to -0.05,0 on M2 Board Dimensions
60,-1 to 0,20 on M2 Board Dimensions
